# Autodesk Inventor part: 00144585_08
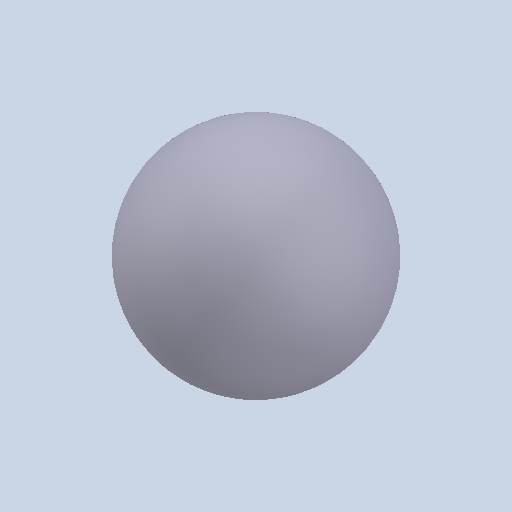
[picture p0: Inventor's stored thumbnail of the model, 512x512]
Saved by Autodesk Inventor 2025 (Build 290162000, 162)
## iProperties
Created: 2021-02
Part Number: 00144585_08
Material: Generico
Document SubType Name: Modeling
Designer: Ryzen5700u
Density: 1 g/cm^3
Appearance: Default
Author: Ryzen5700u
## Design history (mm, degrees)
feature "Solido1"
node "Solido2"
